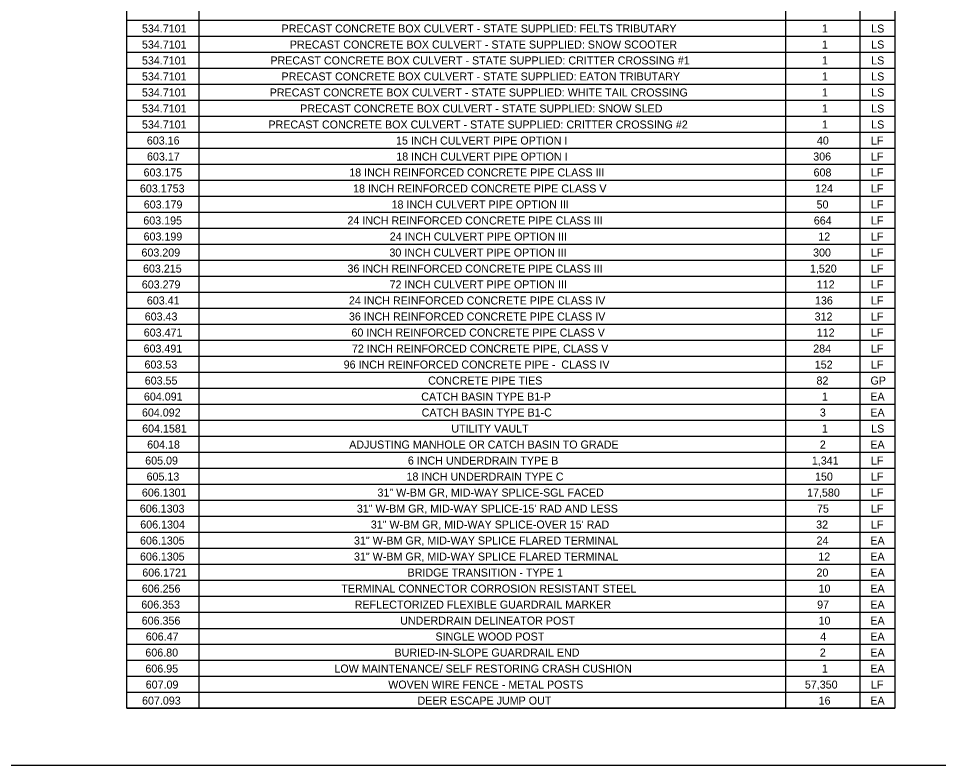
# Model space of a CAD drawing. Extents: x -18.7 to 5.6, y -2.7 to 4.
# Drawn here: x -16.637 to -15.505, y 2.172 to 3.091 of the extents above; entities that cross this region are included whole.
import ezdxf

# ---------------------------------------------------------------- set-up
doc = ezdxf.new("R2010")
doc.units = 0
doc.layers.add('ANNOTATION', color=7, linetype='Continuous')
doc.layers.add('BORDER', color=7, linetype='Continuous')

msp = doc.modelspace()

# ---------------------------------------------------------------- linework, layer by layer
at = {"layer": 'ANNOTATION'}
msp.add_lwpolyline([(-17.663, 4.0141), (-13.3075, 4.0141), (-13.3075, 2.1719), (-17.663, 2.1719)], close=True, dxfattribs=at)
at = {"layer": 'BORDER'}
for p, q in [((-16.415, 3.9551), (-16.415, 2.2424)), ((-15.6937, 3.9551), (-15.6937, 2.2424)), ((-15.6023, 3.9551), (-15.6023, 2.2424)), ((-16.5036, 3.0889), (-15.5593, 3.0889)), ((-16.5036, 3.0692), (-15.5593, 3.0692)), ((-16.5036, 3.0495), (-15.5593, 3.0495)), ((-16.5036, 3.0299), (-15.5593, 3.0299)), ((-16.5036, 3.0102), (-15.5593, 3.0102)), ((-16.5036, 2.9905), (-15.5593, 2.9905)), ((-16.5036, 2.9708), (-15.5593, 2.9708)), ((-16.5036, 2.9511), (-15.5593, 2.9511)), ((-16.5036, 2.9314), (-15.5593, 2.9314)), ((-16.5036, 2.9117), (-15.5593, 2.9117)), ((-16.5036, 2.8921), (-15.5593, 2.8921)), ((-16.5036, 2.8724), (-15.5593, 2.8724)), ((-16.5036, 2.8527), (-15.5593, 2.8527)), ((-16.5036, 2.833), (-15.5593, 2.833)), ((-16.5036, 2.8133), (-15.5593, 2.8133)), ((-16.5036, 2.7936), (-15.5593, 2.7936)), ((-16.5036, 2.7739), (-15.5593, 2.7739)), ((-16.5036, 2.7543), (-15.5593, 2.7543)), ((-16.5036, 2.7346), (-15.5593, 2.7346)), ((-16.5036, 2.7149), (-15.5593, 2.7149)), ((-16.5036, 2.6952), (-15.5593, 2.6952)), ((-16.5036, 2.6755), (-15.5593, 2.6755)), ((-16.5036, 2.6558), (-15.5593, 2.6558)), ((-16.5036, 2.6361), (-15.5593, 2.6361)), ((-16.5036, 2.6165), (-15.5593, 2.6165)), ((-16.5036, 2.5968), (-15.5593, 2.5968)), ((-16.5036, 2.5771), (-15.5593, 2.5771)), ((-16.5036, 2.5574), (-15.5593, 2.5574)), ((-16.5036, 2.5377), (-15.5593, 2.5377)), ((-16.5036, 2.518), (-15.5593, 2.518)), ((-16.5036, 2.4983), (-15.5593, 2.4983)), ((-16.5036, 2.4787), (-15.5593, 2.4787)), ((-16.5036, 2.459), (-15.5593, 2.459)), ((-16.5036, 2.4393), (-15.5593, 2.4393)), ((-16.5036, 2.4196), (-15.5593, 2.4196)), ((-16.5036, 2.3999), (-15.5593, 2.3999)), ((-16.5036, 2.3802), (-15.5593, 2.3802)), ((-16.5036, 2.3605), (-15.5593, 2.3605)), ((-16.5036, 2.3408), (-15.5593, 2.3408)), ((-16.5036, 2.3212), (-15.5593, 2.3212)), ((-16.5036, 2.3015), (-15.5593, 2.3015)), ((-16.5036, 2.2818), (-15.5593, 2.2818)), ((-16.5036, 2.2621), (-15.5593, 2.2621)), ((-16.5036, 2.2424), (-15.5593, 2.2424))]:
    msp.add_line(p, q, dxfattribs=at)
msp.add_lwpolyline([(-16.5036, 3.9748), (-15.5593, 3.9748), (-15.5593, 2.2424), (-16.5036, 2.2424)], close=True, dxfattribs=at)

# ---------------------------------------------------------------- texts
at = {"layer": 'ANNOTATION'}
for s, height, p in [('534.7101', 0.00984, (-16.485, 3.0738)), ('PRECAST CONCRETE BOX CULVERT - STATE SUPPLIED: FELTS TRIBUTARY', 0.009843, (-16.3133, 3.0738)), ('1', 0.00984, (-15.649, 3.0738)), ('LS', 0.00984, (-15.5883, 3.0738)), ('534.7101', 0.00984, (-16.485, 3.0541)), ('PRECAST CONCRETE BOX CULVERT - STATE SUPPLIED: SNOW SCOOTER', 0.009843, (-16.3032, 3.0541)), ('1', 0.00984, (-15.649, 3.0541)), ('LS', 0.00984, (-15.5883, 3.0541)), ('534.7101', 0.00984, (-16.485, 3.0345)), ('PRECAST CONCRETE BOX CULVERT - STATE SUPPLIED: CRITTER CROSSING #1', 0.009843, (-16.3271, 3.0345)), ('1', 0.00984, (-15.649, 3.0345)), ('LS', 0.00984, (-15.5883, 3.0345)), ('534.7101', 0.00984, (-16.485, 3.0148)), ('PRECAST CONCRETE BOX CULVERT - STATE SUPPLIED: EATON TRIBUTARY', 0.009843, (-16.3134, 3.0148)), ('1', 0.00984, (-15.649, 3.0148)), ('LS', 0.00984, (-15.5883, 3.0148)), ('534.7101', 0.00984, (-16.485, 2.9951)), ('PRECAST CONCRETE BOX CULVERT - STATE SUPPLIED: WHITE TAIL CROSSING', 0.009843, (-16.3279, 2.9951)), ('1', 0.00984, (-15.649, 2.9951)), ('LS', 0.00984, (-15.5883, 2.9951)), ('534.7101', 0.00984, (-16.485, 2.9754)), ('PRECAST CONCRETE BOX CULVERT - STATE SUPPLIED: SNOW SLED', 0.009843, (-16.2904, 2.9754)), ('1', 0.00984, (-15.649, 2.9754)), ('LS', 0.00984, (-15.5883, 2.9754)), ('534.7101', 0.00984, (-16.485, 2.9557)), ('PRECAST CONCRETE BOX CULVERT - STATE SUPPLIED: CRITTER CROSSING #2', 0.009843, (-16.3295, 2.9557)), ('1', 0.00984, (-15.649, 2.9557)), ('LS', 0.00984, (-15.5883, 2.9557)), ('603.16', 0.00984, (-16.479, 2.936)), ('15 INCH CULVERT PIPE OPTION I', 0.009843, (-16.1726, 2.936)), ('40', 0.00984, (-15.6551, 2.936)), ('LF', 0.00984, (-15.5887, 2.936)), ('603.17', 0.00984, (-16.4788, 2.9163)), ('18 INCH CULVERT PIPE OPTION I', 0.009843, (-16.1723, 2.9163)), ('306', 0.00984, (-15.6596, 2.9163)), ('LF', 0.00984, (-15.5887, 2.9163)), ('603.175', 0.00984, (-16.483, 2.8967)), ('18 INCH REINFORCED CONCRETE PIPE CLASS III', 0.009843, (-16.2301, 2.8967)), ('608', 0.00984, (-15.6592, 2.8967)), ('LF', 0.00984, (-15.5887, 2.8967)), ('603.1753', 0.00984, (-16.4875, 2.877)), ('18 INCH REINFORCED CONCRETE PIPE CLASS V', 0.009843, (-16.2254, 2.877)), ('124', 0.00984, (-15.6574, 2.877)), ('LF', 0.00984, (-15.5887, 2.877)), ('603.179', 0.00984, (-16.4828, 2.8573)), ('18 INCH CULVERT PIPE OPTION III', 0.009843, (-16.1781, 2.8573)), ('50', 0.00984, (-15.6555, 2.8573)), ('LF', 0.00984, (-15.5887, 2.8573)), ('603.195', 0.00984, (-16.4833, 2.8376)), ('24 INCH REINFORCED CONCRETE PIPE CLASS III', 0.009843, (-16.2323, 2.8376)), ('664', 0.00984, (-15.6589, 2.8376)), ('LF', 0.00984, (-15.5887, 2.8376)), ('603.199', 0.00984, (-16.483, 2.8179)), ('24 INCH CULVERT PIPE OPTION III', 0.009843, (-16.1803, 2.8179)), ('12', 0.00984, (-15.6534, 2.8179)), ('LF', 0.00984, (-15.5887, 2.8179)), ('603.209', 0.00984, (-16.4856, 2.7982)), ('30 INCH CULVERT PIPE OPTION III', 0.009843, (-16.1807, 2.7982)), ('300', 0.00984, (-15.6598, 2.7982)), ('LF', 0.00984, (-15.5887, 2.7982)), ('603.215', 0.00984, (-16.4837, 2.7785)), ('36 INCH REINFORCED CONCRETE PIPE CLASS III', 0.009843, (-16.2323, 2.7785)), ('1,520', 0.00984, (-15.6637, 2.7785)), ('LF', 0.00984, (-15.5887, 2.7785)), ('603.279', 0.00984, (-16.4852, 2.7589)), ('72 INCH CULVERT PIPE OPTION III', 0.009843, (-16.1805, 2.7589)), ('112', 0.00984, (-15.6553, 2.7589)), ('LF', 0.00984, (-15.5887, 2.7589)), ('603.41', 0.00984, (-16.479, 2.7392)), ('24 INCH REINFORCED CONCRETE PIPE CLASS IV', 0.009843, (-16.2305, 2.7392)), ('136', 0.00984, (-15.6575, 2.7392)), ('LF', 0.00984, (-15.5887, 2.7392)), ('603.43', 0.00984, (-16.4816, 2.7195)), ('36 INCH REINFORCED CONCRETE PIPE CLASS IV', 0.009843, (-16.2305, 2.7195)), ('312', 0.00984, (-15.6579, 2.7195)), ('LF', 0.00984, (-15.5887, 2.7195)), ('603.471', 0.00984, (-16.4828, 2.6998)), ('60 INCH REINFORCED CONCRETE PIPE CLASS V', 0.009843, (-16.2274, 2.6998)), ('112', 0.00984, (-15.6553, 2.6998)), ('LF', 0.00984, (-15.5887, 2.6998)), ('603.491', 0.00984, (-16.483, 2.6801)), ('72 INCH REINFORCED CONCRETE PIPE, CLASS V', 0.009843, (-16.2268, 2.6801)), ('284', 0.00984, (-15.6596, 2.6801)), ('LF', 0.00984, (-15.5887, 2.6801)), ('603.53', 0.00984, (-16.4819, 2.6604)), ('96 INCH REINFORCED CONCRETE PIPE -  CLASS IV', 0.009843, (-16.237, 2.6604)), ('152', 0.00984, (-15.6577, 2.6604)), ('LF', 0.00984, (-15.5887, 2.6604)), ('603.55', 0.00984, (-16.4816, 2.6407)), ('CONCRETE PIPE TIES', 0.009843, (-16.1331, 2.6407)), ('82', 0.00984, (-15.6556, 2.6407)), ('GP', 0.00984, (-15.5892, 2.6407)), ('604.091', 0.00984, (-16.4826, 2.621)), ('CATCH BASIN TYPE B1-P', 0.009843, (-16.1416, 2.621)), ('1', 0.00984, (-15.649, 2.621)), ('EA', 0.00984, (-15.5894, 2.621)), ('604.092', 0.00984, (-16.485, 2.6014)), ('CATCH BASIN TYPE B1-C', 0.009843, (-16.1411, 2.6014)), ('3', 0.00984, (-15.6515, 2.6014)), ('EA', 0.00984, (-15.5894, 2.6014)), ('604.1581', 0.00984, (-16.4848, 2.5817)), ('UTILITY VAULT', 0.009843, (-16.1046, 2.5817)), ('1', 0.00984, (-15.649, 2.5817)), ('LS', 0.00984, (-15.5883, 2.5817)), ('604.18', 0.00984, (-16.4786, 2.562)), ('ADJUSTING MANHOLE OR CATCH BASIN TO GRADE', 0.009843, (-16.2302, 2.562)), ('2', 0.00984, (-15.6515, 2.562)), ('EA', 0.00984, (-15.5894, 2.562)), ('605.09', 0.00984, (-16.481, 2.5423)), ('6 INCH UNDERDRAIN TYPE B', 0.009843, (-16.158, 2.5423)), ('1,341', 0.00984, (-15.6613, 2.5423)), ('LF', 0.00984, (-15.5887, 2.5423)), ('605.13', 0.00984, (-16.4793, 2.5226)), ('18 INCH UNDERDRAIN TYPE C', 0.009843, (-16.1597, 2.5226)), ('150', 0.00984, (-15.6574, 2.5226)), ('LF', 0.00984, (-15.5887, 2.5226)), ('606.1301', 0.00984, (-16.4851, 2.5029)), ('31" W-BM GR, MID-WAY SPLICE-SGL FACED', 0.009843, (-16.1954, 2.5029)), ('17,580', 0.00984, (-15.6672, 2.5029)), ('LF', 0.00984, (-15.5887, 2.5029)), ('606.1303', 0.00984, (-16.4876, 2.4832)), ('31" W-BM GR, MID-WAY SPLICE-15\' RAD AND LESS', 0.009843, (-16.2208, 2.4832)), ('75', 0.00984, (-15.655, 2.4832)), ('LF', 0.00984, (-15.5887, 2.4832)), ('606.1304', 0.00984, (-16.4871, 2.4636)), ('31" W-BM GR, MID-WAY SPLICE-OVER 15\' RAD', 0.009843, (-16.2036, 2.4636)), ('32', 0.00984, (-15.656, 2.4636)), ('LF', 0.00984, (-15.5887, 2.4636)), ('606.1305', 0.00984, (-16.4874, 2.4439)), ('31" W-BM GR, MID-WAY SPLICE FLARED TERMINAL', 0.009843, (-16.2243, 2.4439)), ('24', 0.00984, (-15.6555, 2.4439)), ('EA', 0.00984, (-15.5894, 2.4439)), ('606.1305', 0.00984, (-16.4874, 2.4242)), ('31" W-BM GR, MID-WAY SPLICE FLARED TERMINAL', 0.009843, (-16.2243, 2.4242)), ('12', 0.00984, (-15.6534, 2.4242)), ('EA', 0.00984, (-15.5894, 2.4242)), ('606.1721', 0.00984, (-16.4846, 2.4045)), ('BRIDGE TRANSITION - TYPE 1', 0.009843, (-16.1584, 2.4045)), ('20', 0.00984, (-15.6556, 2.4045)), ('EA', 0.00984, (-15.5894, 2.4045)), ('606.256', 0.00984, (-16.4852, 2.3848)), ('TERMINAL CONNECTOR CORROSION RESISTANT STEEL', 0.009843, (-16.2399, 2.3848)), ('10', 0.00984, (-15.6531, 2.3848)), ('EA', 0.00984, (-15.5894, 2.3848)), ('606.353', 0.00984, (-16.4858, 2.3651)), ('REFLECTORIZED FLEXIBLE GUARDRAIL MARKER', 0.009843, (-16.2234, 2.3651)), ('97', 0.00984, (-15.6548, 2.3651)), ('EA', 0.00984, (-15.5894, 2.3651)), ('606.356', 0.00984, (-16.4853, 2.3454)), ('UNDERDRAIN DELINEATOR POST', 0.009843, (-16.1675, 2.3454)), ('10', 0.00984, (-15.6531, 2.3454)), ('EA', 0.00984, (-15.5894, 2.3454)), ('606.47', 0.00984, (-16.4803, 2.3258)), ('SINGLE WOOD POST', 0.009843, (-16.1241, 2.3258)), ('4', 0.00984, (-15.651, 2.3258)), ('EA', 0.00984, (-15.5894, 2.3258)), ('606.80', 0.00984, (-16.4808, 2.3061)), ('BURIED-IN-SLOPE GUARDRAIL END', 0.009843, (-16.1745, 2.3061)), ('2', 0.00984, (-15.6515, 2.3061)), ('EA', 0.00984, (-15.5894, 2.3061)), ('606.95', 0.00984, (-16.4808, 2.2864)), ('LOW MAINTENANCE/ SELF RESTORING CRASH CUSHION', 0.009843, (-16.2484, 2.2864)), ('1', 0.00984, (-15.649, 2.2864)), ('EA', 0.00984, (-15.5894, 2.2864)), ('607.09', 0.00984, (-16.4804, 2.2667)), ('WOVEN WIRE FENCE - METAL POSTS', 0.009843, (-16.1822, 2.2667)), ('57,350', 0.00984, (-15.6699, 2.2667)), ('LF', 0.00984, (-15.5887, 2.2667)), ('607.093', 0.00984, (-16.4849, 2.247)), ('DEER ESCAPE JUMP OUT', 0.009843, (-16.1462, 2.247)), ('16', 0.00984, (-15.653, 2.247)), ('EA', 0.00984, (-15.5894, 2.247))]:
    msp.add_text(s, height=height, dxfattribs=at).set_placement(p)

doc.saveas('drawing.dxf')
